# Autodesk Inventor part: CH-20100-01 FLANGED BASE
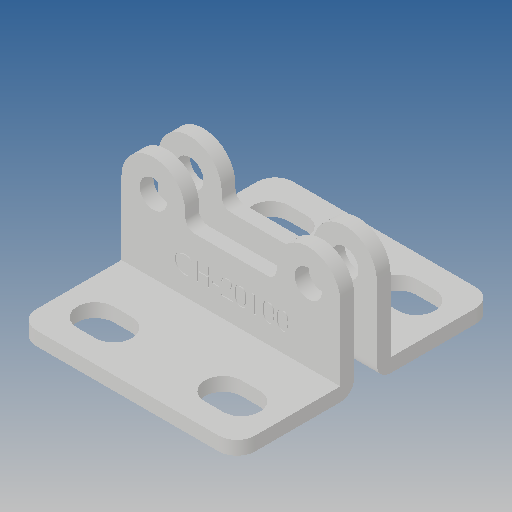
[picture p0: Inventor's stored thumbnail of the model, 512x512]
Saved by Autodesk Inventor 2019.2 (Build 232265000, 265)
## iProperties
Created: 2012-09
Part Number: CH-20100-01 FLANGED BASE
Material: Ogólny
Document SubType Name: Modeling
Designer: CADENGINEERING4
Density: 1 g/cm^3
Appearance: Domyślna
Author: CADENGINEERING4
Revision Number: ÈÎºÎ
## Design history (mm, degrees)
feature "ÇÐ³ý-À­Éì2"
feature "ÇÐ³ý-À­Éì5"
node "Bryła1"
node "Bryła2"
